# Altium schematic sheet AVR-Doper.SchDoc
size A4
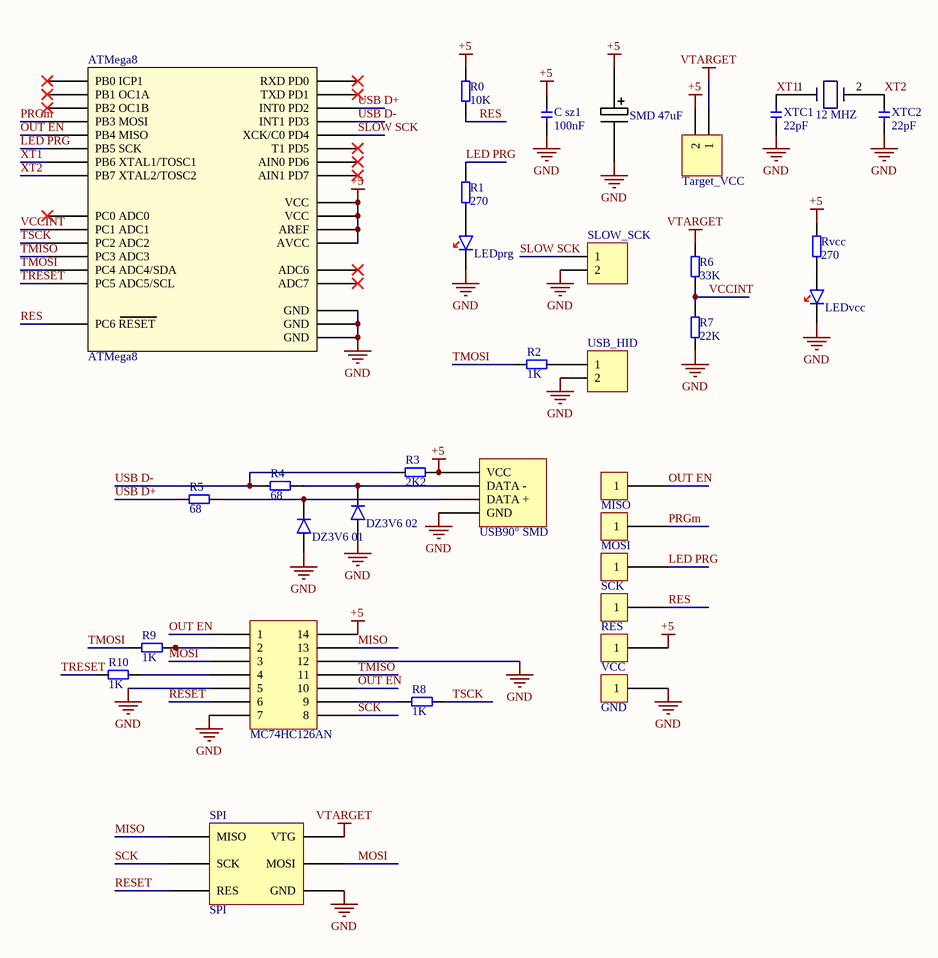
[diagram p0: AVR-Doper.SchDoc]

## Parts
?_MHZ  12 MHZ  [Quartz]
ATMega8  ATMega8  [ATMega8]
C_sz1  value 100nF  [SM 3216[1206]]  (hidden comment: Cap)
DZ3V6_01  Diode  [DO-80]  (value not drawn)
DZ3V6_02  Diode  [DO-80]  (value not drawn)
GND  Mérőpont  [Mérőpont]  (value not drawn)
LEDprg  LED  [SM 3216[1206] - pol]  (value not drawn)
LEDvcc  LED  [SM 3216[1206] - pol]  (value not drawn)
MC74HC126AN  SMD 14 láb  [SMD 14 láb]  (value not drawn)
MISO  Mérőpont  [Mérőpont]  (value not drawn)
MOSI  Mérőpont  [Mérőpont]  (value not drawn)
R0  value 10K  [SM 3216[1206]]  (hidden comment: Res)
R1  value 270  [SM 3216[1206]]  (hidden comment: Res)
R2  value 1K  [SM 3216[1206]]  (hidden comment: Res)
R3  value 2K2  [SM 3216[1206]]  (hidden comment: Res)
R4  value 68  [SM 3216[1206]]  (hidden comment: Res)
R5  value 68  [SM 3216[1206]]  (hidden comment: Res)
R6  value 33K  [SM 3216[1206]]  (hidden comment: Res)
R7  value 22K  [SM 3216[1206]]  (hidden comment: Res)
R8  value 1K  [SM 3216[1206]]  (hidden comment: Res)
R9  value 1K  [SM 3216[1206]]  (hidden comment: Res)
R10  value 1K  [SM 3216[1206]]  (hidden comment: Res)
RES  Mérőpont  [Mérőpont]  (value not drawn)
Rvcc  value 270  [SM 3216[1206]]  (hidden comment: Res)
SCK  Mérőpont  [Mérőpont]  (value not drawn)
SLOW_SCK  Header 2  [HDR1X2]  (value not drawn)
SMD_47uF  SMD 47uF  [SMD 47uF]  (value not drawn)
SPI  SPI  [SPI]  (value not drawn)
Target_VCC  Header 2  [HDR1X2]  (value not drawn)
USB90°_SMD  USB90° SMD  [USB90° SMD]  (value not drawn)
USB_HID  Header 2  [HDR1X2]  (value not drawn)
VCC  Mérőpont  [Mérőpont]  (value not drawn)
XTC1  value 22pF  [SM 3216[1206]]  (hidden comment: Cap)
XTC2  value 22pF  [SM 3216[1206]]  (hidden comment: Cap)

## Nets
+5: ATMega8.4(VCC) ATMega8.6(VCC) ATMega8.18(AVCC) ATMega8.20(AREF) C_sz1.1 MC74HC126AN.14 R0.2 R3.1 Rvcc.2 SMD_47uF.1 Target_VCC.2 USB90°_SMD.1(VCC) VCC.1
GND: ATMega8.3(GND) ATMega8.5(GND) ATMega8.21(GND) C_sz1.2 DZ3V6_01.1(anód) DZ3V6_02.1(anód) GND.1 LEDprg.2(katód) LEDvcc.2(katód) MC74HC126AN.5 MC74HC126AN.7 MC74HC126AN.12 R7.2 SLOW_SCK.2 SMD_47uF.2 SPI.6(GND) USB90°_SMD.4(GND) USB_HID.2 XTC1.2 XTC2.2
VTARGET: R6.1 SPI.2(VTG) Target_VCC.1
LED PRG: ATMega8.17(PB5_SCK) R1.2 SCK.1
MISO: MC74HC126AN.13 SPI.1(MISO)
MOSI: MC74HC126AN.3 SPI.4(MOSI)
OUT EN: ATMega8.16(PB4_MISO) MC74HC126AN.1 MC74HC126AN.10 MISO.1
PRGm: ATMega8.15(PB3_MOSI) MOSI.1
RES: ATMega8.29(PC6_RESET) R0.1 RES.1
RESET: MC74HC126AN.6 SPI.5(RES)
SCK: MC74HC126AN.8 SPI.3(SCK)
SLOW SCK: ATMega8.2(XCK/C0_PD4) SLOW_SCK.1
TMISO: ATMega8.26(PC3_ADC3) MC74HC126AN.11
TMOSI: ATMega8.27(PC4_ADC4/SDA) R2.2 R9.1
TRESET: ATMega8.28(PC5_ADC5/SCL) R10.1
TSCK: ATMega8.25(PC2_ADC2) R8.2
USB D+: ATMega8.32(INT0_PD2) R5.2
USB D-: ATMega8.1(INT1_PD3) R3.2 R4.2
VCCINT: ATMega8.24(PC1_ADC1) R6.2 R7.1
XT1: ?_MHZ.1 ATMega8.7(PB6_XTAL1/TOSC1) XTC1.1
XT2: ?_MHZ.2 ATMega8.8(PB7_XTAL2/TOSC2) XTC2.1
NetDZ3V6_01_2: DZ3V6_01.2(katód) R5.1 USB90°_SMD.3(DATA_+)
NetDZ3V6_02_2: DZ3V6_02.2(katód) R4.1 USB90°_SMD.2(DATA_-)
NetLEDprg_1: LEDprg.1(anód) R1.1
NetLEDvcc_1: LEDvcc.1(anód) Rvcc.1
NetMC74HC126AN_2: MC74HC126AN.2 R9.2
NetMC74HC126AN_4: MC74HC126AN.4 R10.2
NetMC74HC126AN_9: MC74HC126AN.9 R8.1
NetR2_1: R2.1 USB_HID.1

Not connected (* = marked no-connect by the designer): ATMega8 9(T1_PD5)* 10(AIN0_PD6)* 11(AIN1_PD7)* 12(PB0_ICP1)* 13(PB1_OC1A)* 14(PB2_OC1B)* 19(ADC6)* 22(ADC7)* 23(PC0_ADC0)* 30(RXD_PD0)* 31(TXD_PD1)*

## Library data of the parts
?_MHZ = Quartz: SMD
C_sz1 XTC1 XTC2 = Cap: Capacitor
R0-R10 Rvcc = Res: Resistor
SLOW_SCK Target_VCC USB_HID = Header 2: Header, 2-Pin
